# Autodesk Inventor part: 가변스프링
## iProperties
Created: 2015-03
Part Number: 가변스프링
Document SubType Name: Modeling
Designer: Administrator
Density: 7.87 g/cm^3
Material: 탄소강
Mass: 47.8301 g
Surface Area: 61.9783 cm^2
Volume: 6.07752 cm^3
Author: Administrator
